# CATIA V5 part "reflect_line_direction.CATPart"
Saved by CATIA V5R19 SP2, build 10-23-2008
Part number: Part1
Bounding box of the stored display mesh (mm): x -62.196 to 127.181, y -135.683 to 227.819, z -30.803 to 139.878
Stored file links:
  D:\upload\reflect_line_direction.CATPart
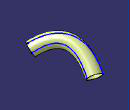
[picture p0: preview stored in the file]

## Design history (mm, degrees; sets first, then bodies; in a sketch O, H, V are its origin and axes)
AxisSystem1: origin (0, 0, 0), X (1, 0, 0), Y (0, 1, 0), Z (0, 0, 1)
Set1
  DatumSurface1
  DatumCurve1
  DatumCurve2
Body1 (main body)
